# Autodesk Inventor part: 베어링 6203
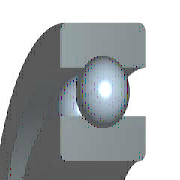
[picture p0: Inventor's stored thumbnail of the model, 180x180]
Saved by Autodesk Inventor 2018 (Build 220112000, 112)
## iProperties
Created: 2012-02
Part Number: 베어링 6203
Material: 강철, 연강
Description: 깊은 그루브 볼 베어링
Document SubType Name: Modeling
Standard: KS B 2023
Designer: mduedu
Standards Organization: KS
Language: ko-KR
Size Designation: 6203 - 17 x 40 x 12
Categories: <MemberInstance><Categories><Category DisplayName="샤프트 부품" InternalName="7f7aeb1f-a693-4053-b835-cee3144e0d98" Mnemonic="SHFT"><Category DisplayName="베어링" Inter
Density: 7.85 g/cm^3
Appearance: 노란색
Mass: 64.8982 g
Surface Area: 64.3582 cm^2
Volume: 8.26729 cm^3
IsCustomPart: 1
Author: mduedu
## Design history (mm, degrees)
sketch "스케치" dims "d0" = 5.98 (= -0.26 x WD + 0.26 x BD)
  geometry: L1 (3.01, 14.25)-(8.99, 14.25); L2 (6, 14.25)-(6, 11.26); L3 (6, 14.25)-(6, 17.24); L4 (3.778, 12.249)-(0, 12.249); L5 (0, 8.5)-(12, 8.5); L6 (3.778, 16.251)-(0, 16.251); L7 (0, 20)-(12, 20); L8 (12, 8.5)-(12, 12.249); L9 (8.222, 12.249)-(12, 12.249); L10 (8.222, 16.251)-(12, 16.251); L11 (12, 20)-(12, 16.251); L12 (-1.4, 0)-(8.4, 0) reference; L13 (0, -0.3)-(0, 5.3) reference
  constraints: 22 end point, 4 point on line, 2 collinear, 2 perpendicular, 2 symmetric about line, 1 midpoint, 1 parallel, 14 other
  dimensions: "d9" = 17 diameter of L5 L12 (= WD); "d11" = 40 diameter of L7 L12 (= BD); "d12" = 12 distance between parallel lines of L8 L13 (= KB); "d13" = 24.498 diameter of L9 L12 (= 0.326 x BD + 0.674 x WD)
revolve "본체" stored, may be unused: angle "d6" = 90 deg
revolve "볼" stored, may be unused: angle "d7" = 90 deg
pattern_circular "IDS_ARRAYBALL[SIMPL:T]" dims angle "d3" = 360 deg
body "Solid1"
fillet "모깎기1" dims "d1" = 0.6 (= KRS)
other parameters: "WD" = 17 [user parameter; used in 5 equation terms], "BD" = 40 [user parameter; used in 5 equation terms], "KB" = 12 [user parameter; used in 1 equation term], "KRS" = 0.6 [user parameter; used in 1 equation term], "d4" = 0, "d5" = 0, "d8" = 0, "d14" = 0, "d15" = 0, "BBA" = 0 [user parameter], "BC0" = 4750000 [user parameter], "BC" = 9560000 [user parameter], "WR" = 8.5 (= 0.5 x WD) [user parameter]
